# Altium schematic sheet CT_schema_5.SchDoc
size 383 x 311 mm
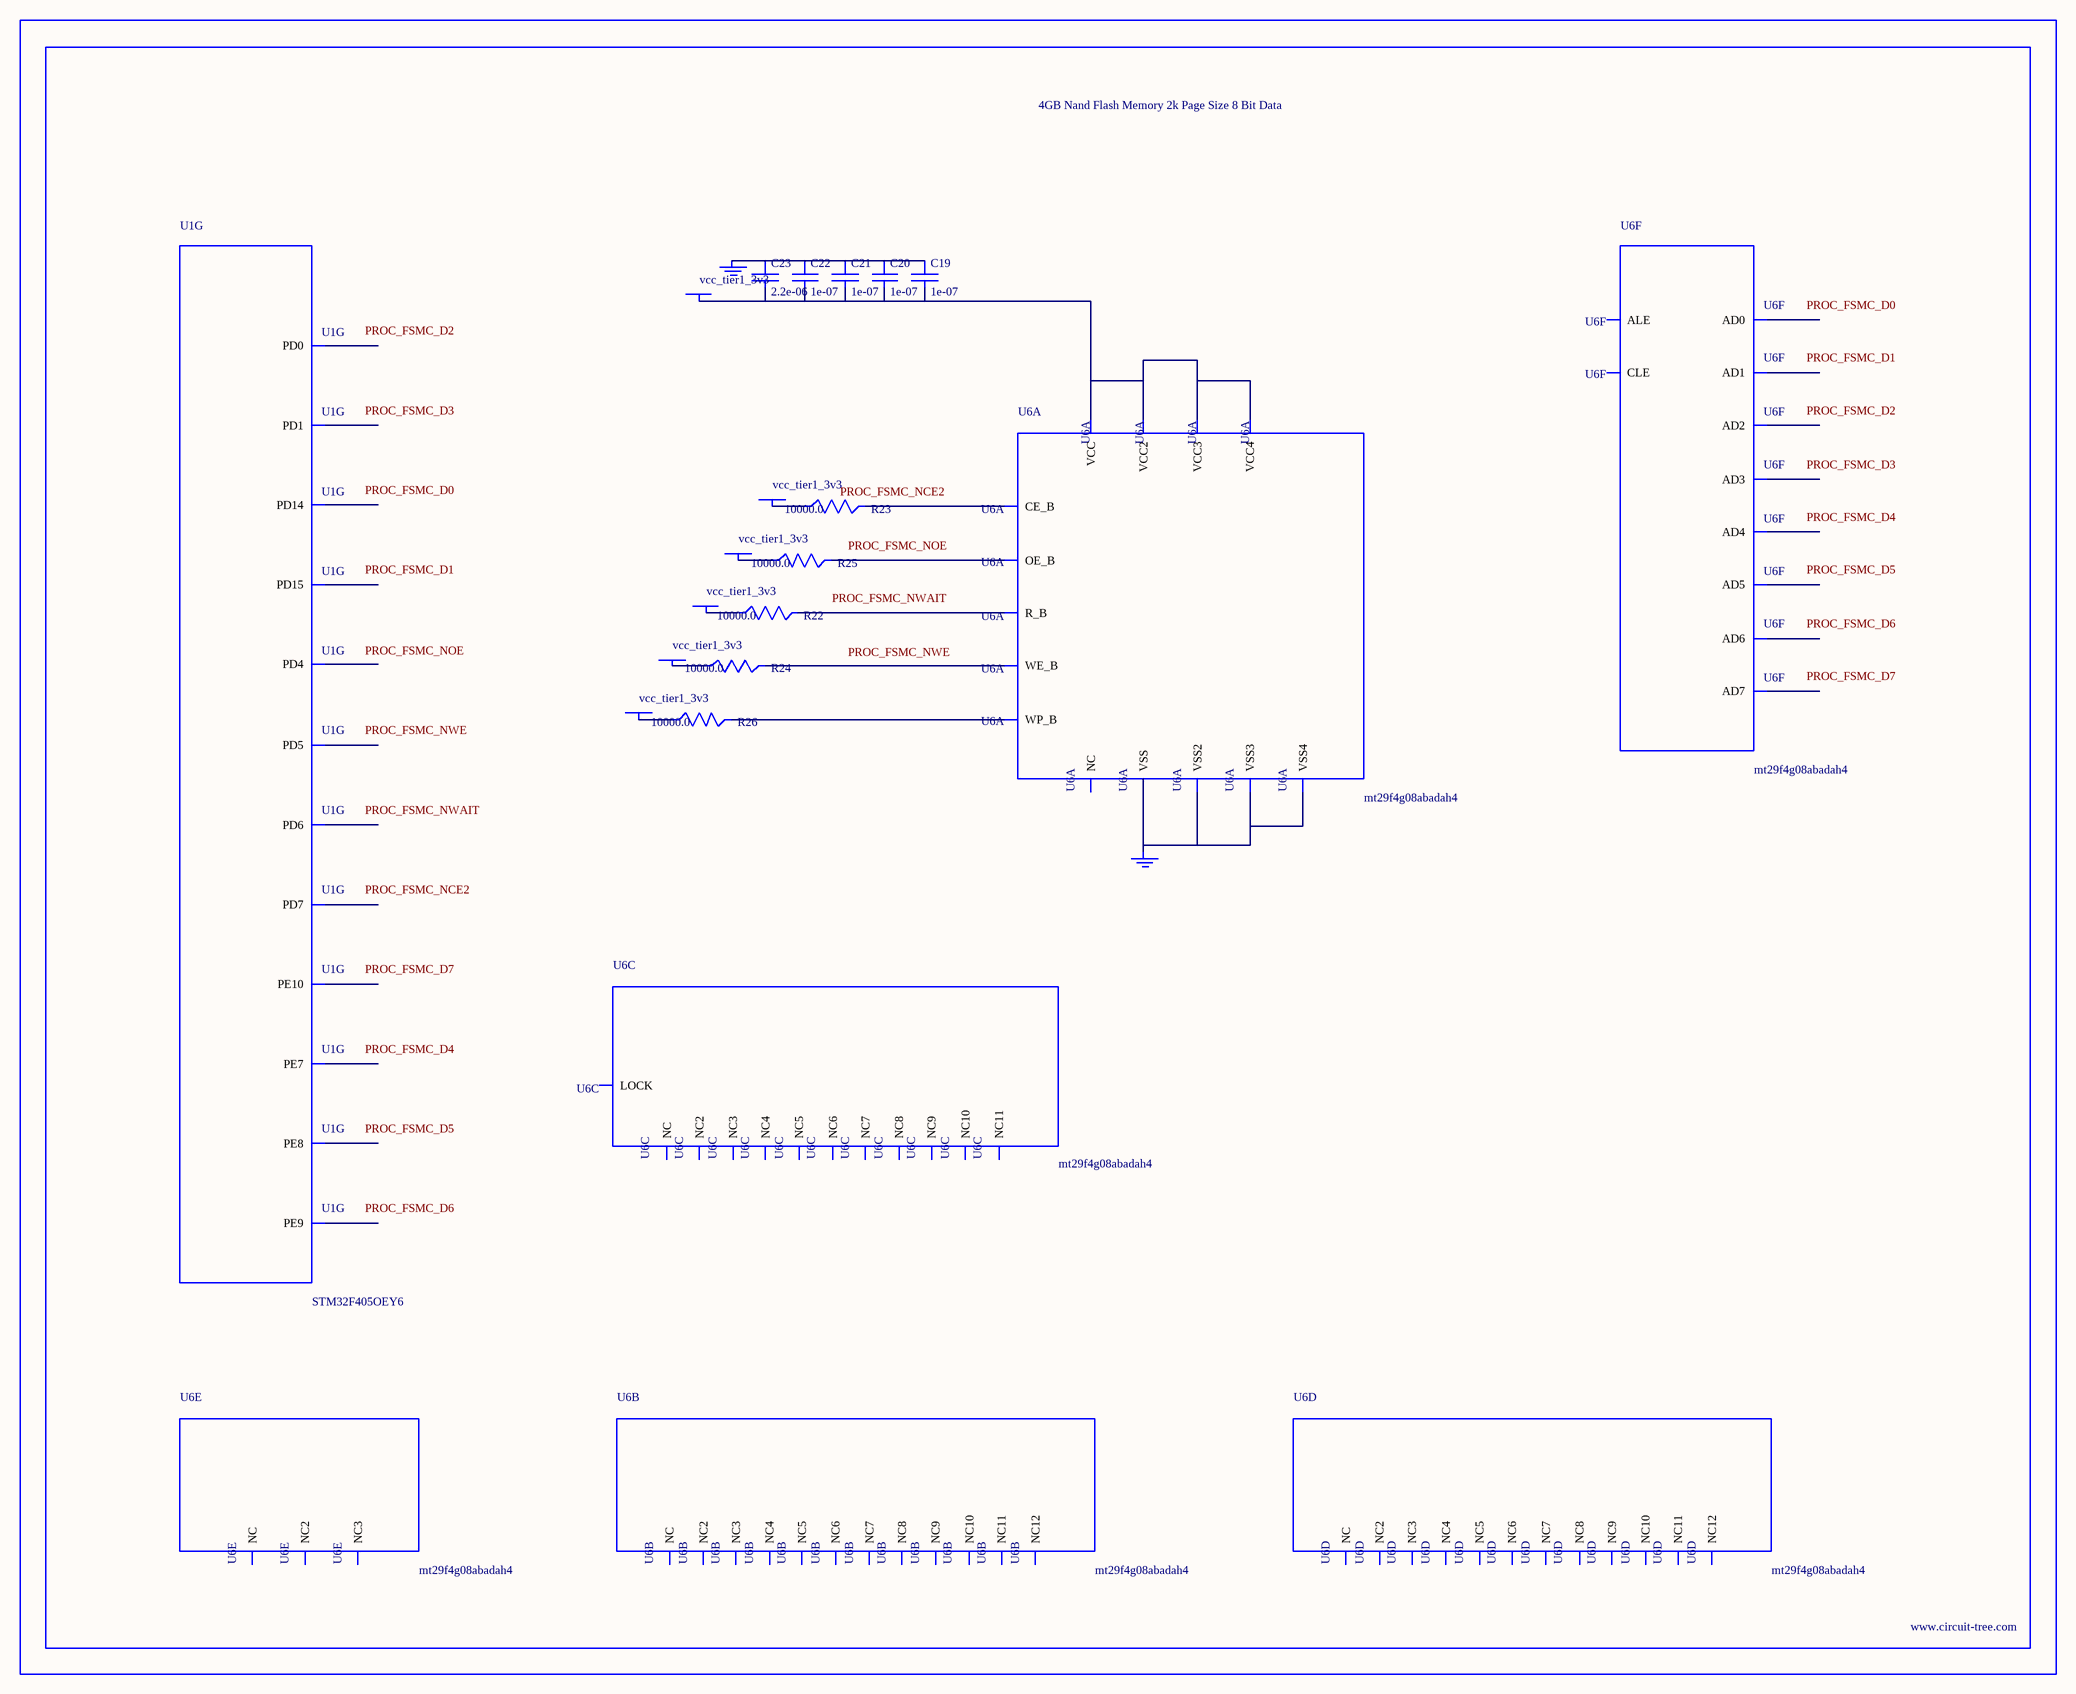
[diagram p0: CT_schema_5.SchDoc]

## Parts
BORDER4  (no value)
C19  1e-07  [C0402]
C20  1e-07  [C0402]
C21  1e-07  [C0402]
C22  1e-07  [C0402]
C23  2.2e-06  [C0603]
GND_INSTANCE_4_0  (no value)
GND_INSTANCE_4_1  (no value)
POWER_INSTANCE_4_0  vcc_tier1_3v3
POWER_INSTANCE_4_1  vcc_tier1_3v3
POWER_INSTANCE_4_2  vcc_tier1_3v3
POWER_INSTANCE_4_3  vcc_tier1_3v3
POWER_INSTANCE_4_4  vcc_tier1_3v3
POWER_INSTANCE_4_5  vcc_tier1_3v3
R22  10000.0  [R0603]
R23  10000.0  [R0603]
R24  10000.0  [R0603]
R25  10000.0  [R0603]
R26  10000.0  [R0603]
U1  STM32F405OEY6  [WLCSP90]  (part G of 8)
U6  mt29f4g08abadah4  [VFBGA-63]  (parts A,B,C,D,E,F of 6)

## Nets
NetC19_1: C19.1 C20.1 C21.1 C22.1 C23.1 GND_INSTANCE_4_0.0(GND)
NetC19_2: C19.2 C20.2 C21.2 C22.2 C23.2 POWER_INSTANCE_4_0.0(PWR) U6.D3(VCC) U6.G4(VCC2) U6.H8(VCC3) U6.J6(VCC4)
NetGND_INSTANCE_4_1_0: GND_INSTANCE_4_1.0(GND) U6.C5(VSS) U6.F7(VSS2) U6.K3(VSS3) U6.K8(VSS4)
NetPOWER_INSTANCE_4_1_0: POWER_INSTANCE_4_1.0(PWR) R22.1
NetPOWER_INSTANCE_4_2_0: POWER_INSTANCE_4_2.0(PWR) R23.1
NetPOWER_INSTANCE_4_3_0: POWER_INSTANCE_4_3.0(PWR) R24.1
NetPOWER_INSTANCE_4_4_0: POWER_INSTANCE_4_4.0(PWR) R25.1
NetPOWER_INSTANCE_4_5_0: POWER_INSTANCE_4_5.0(PWR) R26.1
NetR22_2: R22.2 U6.C8(R_B)
NetR23_2: R23.2 U6.C6(CE_B)
NetR24_2: R24.2 U6.C7(WE_B)
NetR25_2: R25.2 U6.D4(OE_B)
NetR26_2: R26.2 U6.C3(WP_B)

Not connected (* = marked no-connect by the designer): U1 A4(PD4) A5(PD7) B5(PD6) C5(PD1) C6(PD5) D6(PD0) F1(PD15) F2(PD14) F6(PE10) G6(PE7) H6(PE8) J6(PE9); U6 A1(NC) A2(NC3) A9(NC4) A10(NC2) B1(NC5) B9(NC7) B10(NC6) C4(ALE) D5(CLE) D6(NC8) D7(NC9) D8(NC10) E3(NC11) E4(NC12) E5(NC) E6(NC2) E7(NC3) E8(NC4) F3(NC5) F4(NC6) F5(NC7) F6(NC8) F8(NC9) G3(NC) G5(LOCK) G6(NC10) G7(NC11) G8(NC) H3(NC2) H4(AD0) H5(NC3) H6(NC4) H7(NC5) J3(NC6) J4(AD1) J5(NC7) J7(AD5) J8(AD7) K4(AD2) K5(AD3) K6(AD4) K7(AD6) L1(NC8) L2(NC10) L9(NC11) L10(NC9) M1(NC12) M2(NC2) M9(NC3) M10(NC)

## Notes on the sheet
- Labels drawn without touching a wire or pin: PROC_FSMC_D0, PROC_FSMC_D1, PROC_FSMC_D2, PROC_FSMC_D3, PROC_FSMC_D4, PROC_FSMC_D5, PROC_FSMC_D6, PROC_FSMC_D7, PROC_FSMC_NCE2, PROC_FSMC_NOE, PROC_FSMC_NWAIT, PROC_FSMC_NWE

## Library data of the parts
BORDER4 = BORDER_PAGE4
C19-C22 = C0402C104K3RACTU
C23 = C0603C225K8RACTU
GND_INSTANCE_4_0 GND_INSTANCE_4_1 = GND
POWER_INSTANCE_4_0-POWER_INSTANCE_4_5 = PWR
R22-R26 = RC0603JR-0710KL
